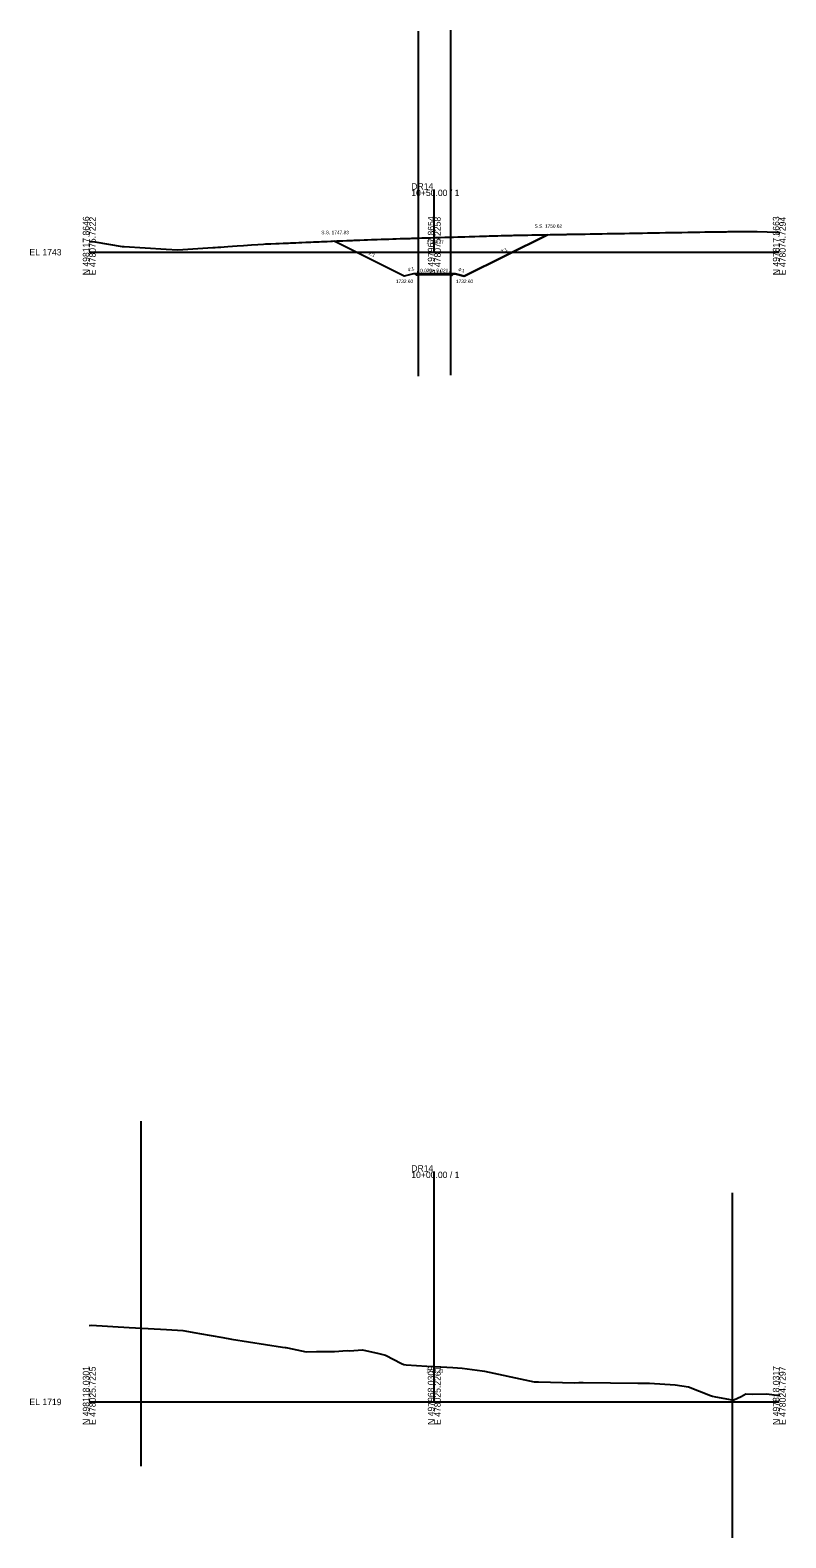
# Model space of a CAD drawing. Extents: x -26 to 303, y -59 to 3067.
# Drawn here: x -26 to 303, y -59 to 597 of the extents above; entities that cross this region are included whole.
import ezdxf

# ---------------------------------------------------------------- set-up
doc = ezdxf.new("R2010")
doc.units = 0
for name, color, linetype in [('Exist Cross Section Cell', 7, 'Continuous'), ('Exist XS Center Line Elevation Label', 7, 'Continuous'), ('Exist XS Ground Line', 7, 'Continuous'), ('Prop XS Ditch Slope Text', 7, 'Continuous'), ('Prop XS Ditch Standard Text', 7, 'Continuous'), ('Prop XS Earthwork Shape', 7, 'Continuous'), ('Prop XS EOT Tick Mark', 7, 'Continuous'), ('Prop XS Finish Grade', 7, 'Continuous'), ('Prop XS Finish Grade Earthwork', 7, 'Continuous'), ('Prop XS Finish Grade Pavement', 7, 'Continuous'), ('Prop XS Pvmt Edge Slope', 7, 'Continuous'), ('Prop XS SE Text', 7, 'Continuous'), ('Prop XS Shoulder Borrow Shape', 7, 'Continuous'), ('Prop XS Side Slope Text', 7, 'Continuous'), ('Prop XS SS Elevation Text', 7, 'Continuous'), ('Prop XS Subgrade Earthwork', 7, 'Continuous'), ('Scratch_Level_6', 7, 'Continuous')]:
    doc.layers.add(name, color=color, linetype=linetype)

msp = doc.modelspace()

# ---------------------------------------------------------------- linework, layer by layer
at = {"layer": 'Exist Cross Section Cell'}
for p, q in [((150, 500), (150, 527.23)), ((0, 500), (150, 500)), ((150, 500), (300, 500)), ((150, 0), (150, 100.16)), ((0, 0), (150, 0)), ((150, 0), (300, 0))]:
    msp.add_line(p, q, dxfattribs=at)
at = {"layer": 'Exist XS Ground Line'}
for points in [[(0, 504.72), (0.95, 504.63), (2.38, 504.49), (14.28, 502.52), (15.11, 502.47), (33.42, 501.31), (38.57, 501.07), (53.74, 502), (54.76, 502.07), (55.9, 502.15), (57.17, 502.25), (58.6, 502.35), (60.21, 502.47), (64.32, 502.76), (67.06, 502.95), (70.47, 503.18), (73.32, 503.37), (75.7, 503.53), (76.56, 503.59), (78.67, 503.67), (79, 503.69), (81.13, 503.77), (81.61, 503.79), (82.17, 503.81), (82.6, 503.83), (84.32, 503.9), (84.92, 503.93), (86.62, 504), (87.49, 504.03), (89.86, 504.14), (91.15, 504.19), (92.01, 504.23), (92.37, 504.24), (94.09, 504.31), (94.94, 504.35), (96.28, 504.4), (97.48, 504.45), (98.62, 504.5), (100, 504.56), (100.97, 504.6), (102.53, 504.67), (103.37, 504.7), (105.04, 504.77), (105.8, 504.8), (107.7, 504.89), (108.47, 504.92), (110.19, 504.99), (111.94, 505.06), (112.69, 505.09), (114.41, 505.16), (115.2, 505.19), (115.97, 505.22), (117.7, 505.29), (119.45, 505.36), (120.2, 505.38), (120.94, 505.41), (122.69, 505.48), (124.48, 505.55), (125.2, 505.57), (126.97, 505.63), (127.7, 505.66), (128.43, 505.68), (130.21, 505.74), (132.01, 505.8), (132.7, 505.83), (133.39, 505.85), (135.2, 505.91), (135.92, 505.93), (137.7, 505.99), (139.51, 506.04), (140.2, 506.07), (140.87, 506.09), (142.7, 506.14), (144.53, 506.2), (145.19, 506.22), (147.05, 506.28), (147.71, 506.3), (148.35, 506.32), (150.2, 506.38), (152.06, 506.43), (152.7, 506.45), (154.58, 506.51), (155.2, 506.53), (155.82, 506.54), (157.7, 506.6), (158.33, 506.62), (160.2, 506.67), (162.11, 506.73), (162.7, 506.75), (163.28, 506.76), (165.2, 506.82), (165.79, 506.84), (167.7, 506.9), (169.63, 506.95), (170.2, 506.97), (172.14, 507.03), (172.7, 507.04), (173.85, 507.08), (174.68, 507.1), (175.2, 507.12), (176.46, 507.15), (177.1, 507.17), (177.7, 507.18), (179.1, 507.22), (179.51, 507.23), (181.89, 507.3), (182.51, 507.31), (183.87, 507.34), (184.59, 507.35), (186.03, 507.38), (187.27, 507.4), (188.3, 507.42), (189.87, 507.45), (190.68, 507.47), (192.42, 507.5), (193.1, 507.51), (194.95, 507.54), (195.55, 507.55), (197.5, 507.59), (197.98, 507.6), (200.45, 507.65), (202.7, 507.69), (203.15, 507.7), (205.2, 507.74), (207.27, 507.77), (207.7, 507.79), (209.79, 507.82), (210.2, 507.83), (212.28, 507.86), (212.7, 507.87), (213.11, 507.88), (215.19, 507.91), (215.62, 507.92), (217.7, 507.95), (219.82, 507.98), (220.2, 507.99), (222.34, 508.03), (222.7, 508.03), (223.06, 508.04), (225.2, 508.08), (225.57, 508.08), (227.69, 508.12), (229.82, 508.15), (230.19, 508.16), (232.35, 508.2), (232.69, 508.2), (234.88, 508.24), (235.2, 508.25), (235.52, 508.25), (237.7, 508.29), (238.03, 508.29), (240.19, 508.33), (240.53, 508.34), (242.7, 508.37), (244.9, 508.41), (245.2, 508.41), (247.97, 508.46), (250.48, 508.51), (252.99, 508.56), (255.49, 508.6), (257.69, 508.64), (260.2, 508.69), (262.69, 508.73), (265.43, 508.78), (267.68, 508.81), (268.06, 508.82), (268.51, 508.82), (270.2, 508.85), (270.79, 508.86), (272.3, 508.88), (273.21, 508.89), (273.81, 508.9), (275.33, 508.92), (277.01, 508.94), (277.78, 508.95), (279.72, 508.97), (280.24, 508.98), (282.38, 509), (282.7, 509), (284.53, 509.02), (285.27, 509.03), (286.18, 509.04), (287.2, 509.05), (289.72, 509.08), (290.43, 509.04), (294.75, 508.86), (298.86, 508.69), (299.59, 508.67), (300, 508.65)], [(0, 33.28), (0.89, 33.39), (17.33, 32.44), (25.55, 31.95), (33.63, 31.57), (40.71, 31.01), (46.39, 30.08), (47.93, 29.78), (58.11, 27.96), (61.85, 27.26), (83.99, 23.84), (85.12, 23.67), (85.48, 23.65), (86.15, 23.49), (94.24, 21.81), (98.77, 21.96), (102.28, 21.92), (106.58, 21.95), (112.07, 22.34), (113.14, 22.18), (118.8, 22.6), (119.41, 22.53), (125.28, 21.18), (128.86, 20.35), (135.71, 16.79), (136.73, 16.33), (137.8, 16.07), (146.81, 15.63), (150, 15.43), (152.79, 15.26), (158.02, 14.93), (162.15, 14.71), (170.85, 13.53), (171.88, 13.32), (191.45, 9.14), (193.39, 8.75), (195.33, 8.79), (211.01, 8.34), (212.89, 8.42), (214.78, 8.51), (238.54, 8.19), (240.72, 8.23), (242.91, 8.22), (243.51, 8.21), (254.66, 7.48), (260.51, 6.53), (270.06, 2.77), (271.02, 2.54), (272.21, 2.28), (277.84, 1.22), (279.28, 0.9), (280.27, 0.91), (283.41, 2.39), (285.49, 3.46), (288.25, 3.34), (294.51, 3.47), (300, 2.77)]]:
    msp.add_lwpolyline(points, dxfattribs=at)
at = {"layer": 'Prop XS Earthwork Shape'}
msp.add_lwpolyline([(197.98, 507.6), (199.15, 507.62), (163.05, 489.6), (159.04, 490.6), (158.3, 490.66), (157.72, 490.08), (157.04, 490.09), (150, 490.23), (142.96, 490.09), (142.28, 490.08), (141.7, 490.66), (140.96, 490.6), (136.95, 489.6), (106.44, 504.83), (107.7, 504.89), (108.47, 504.92), (110.19, 504.99), (111.94, 505.06), (112.69, 505.09), (114.41, 505.16), (115.2, 505.19), (115.97, 505.22), (117.7, 505.29), (119.45, 505.36), (120.2, 505.38), (120.94, 505.41), (122.69, 505.48), (124.48, 505.55), (125.2, 505.57), (126.97, 505.63), (127.7, 505.66), (128.43, 505.68), (130.21, 505.74), (132.01, 505.8), (132.7, 505.83), (133.39, 505.85), (135.2, 505.91), (135.92, 505.93), (137.7, 505.99), (139.51, 506.04), (140.2, 506.07), (140.87, 506.09), (142.7, 506.14), (144.53, 506.2), (145.19, 506.22), (147.05, 506.28), (147.71, 506.3), (148.35, 506.32), (150.2, 506.38), (152.06, 506.43), (152.7, 506.45), (154.58, 506.51), (155.2, 506.53), (155.82, 506.54), (157.7, 506.6), (158.33, 506.62), (160.2, 506.67), (162.11, 506.73), (162.7, 506.75), (163.28, 506.76), (165.2, 506.82), (165.79, 506.84), (167.7, 506.9), (169.63, 506.95), (170.2, 506.97), (172.14, 507.03), (172.7, 507.04), (173.85, 507.08), (174.68, 507.1), (175.2, 507.12), (176.46, 507.15), (177.1, 507.17), (177.7, 507.18), (179.1, 507.22), (179.51, 507.23), (181.89, 507.3), (182.51, 507.31), (183.87, 507.34), (184.59, 507.35), (186.03, 507.38), (187.27, 507.4), (188.3, 507.42), (189.87, 507.45), (190.68, 507.47), (192.42, 507.5), (193.1, 507.51), (194.95, 507.54), (195.55, 507.55), (197.5, 507.59)], close=True, dxfattribs=at)
at = {"layer": 'Prop XS EOT Tick Mark'}
for p, q in [((142.96, 490.76), (142.96, 491.76)), ((157.04, 490.76), (157.04, 491.76))]:
    msp.add_line(p, q, dxfattribs=at)
at = {"layer": 'Prop XS Finish Grade'}
for p, q in [((142.96, 490.76), (141.7, 490.66)), ((157.04, 490.76), (158.3, 490.66))]:
    msp.add_line(p, q, dxfattribs=at)
at = {"layer": 'Prop XS Finish Grade Earthwork'}
for p, q in [((163.05, 489.6), (199.15, 507.62)), ((136.95, 489.6), (106.44, 504.83)), ((140.96, 490.6), (136.95, 489.6)), ((141.7, 490.66), (140.96, 490.6)), ((158.3, 490.66), (159.04, 490.6)), ((159.04, 490.6), (163.05, 489.6))]:
    msp.add_line(p, q, dxfattribs=at)
at = {"layer": 'Prop XS Finish Grade Pavement'}
for p, q in [((142.96, 490.76), (150, 490.9)), ((150, 490.9), (157.04, 490.76))]:
    msp.add_line(p, q, dxfattribs=at)
at = {"layer": 'Prop XS Pvmt Edge Slope'}
for p, q in [((142.96, 490.76), (142.28, 490.08)), ((157.04, 490.76), (157.72, 490.08))]:
    msp.add_line(p, q, dxfattribs=at)
at = {"layer": 'Prop XS Shoulder Borrow Shape'}
for points in [[(142.96, 490.76), (142.28, 490.08), (141.7, 490.66)], [(157.72, 490.08), (158.3, 490.66), (157.04, 490.76)]]:
    msp.add_lwpolyline(points, close=True, dxfattribs=at)
at = {"layer": 'Prop XS Subgrade Earthwork'}
for p, q in [((142.28, 490.08), (141.7, 490.66)), ((142.96, 490.09), (142.28, 490.08)), ((150, 490.23), (142.96, 490.09)), ((157.04, 490.09), (150, 490.23)), ((157.04, 490.09), (157.72, 490.08)), ((157.72, 490.08), (158.3, 490.66))]:
    msp.add_line(p, q, dxfattribs=at)
at = {"layer": 'Scratch_Level_6'}
for p, q in [((142.96, 596.15), (142.96, 446.15)), ((157.04, 596.58), (157.04, 446.58)), ((22.44, 122.14), (22.44, -27.86)), ((279.56, 90.9), (279.56, -59.1))]:
    msp.add_line(p, q, dxfattribs=at)

# ---------------------------------------------------------------- texts
at = {"layer": 'Exist Cross Section Cell'}
for s, p in [('10+50.00 / 1', (140, 524.43)), ('DR14', (140, 527.23)), ('EL 1743', (-26, 498.6)), ('10+00.00 / 1', (140, 97.36)), ('DR14', (140, 100.16)), ('EL 1719', (-26, -1.4))]:
    msp.add_text(s, height=2.8, dxfattribs=at).set_placement(p)
for s, p in [('N 498117.8646', (0, 490)), ('E 478075.7222', (2.8, 490)), ('N 497967.8654', (150, 490)), ('E 478075.2258', (152.8, 490)), ('N 497817.8663', (300, 490)), ('E 478074.7294', (302.8, 490)), ('N 498118.0301', (0, -10)), ('E 478025.7225', (2.8, -10)), ('N 497968.0309', (150, -10)), ('E 478025.2261', (152.8, -10)), ('N 497818.0317', (300, -10)), ('E 478024.7297', (302.8, -10))]:
    msp.add_text(s, height=2.8, rotation=90, dxfattribs=at).set_placement(p)
at = {"layer": 'Exist XS Center Line Elevation Label'}
for s, p in [('1749.37', (146.58, 503.62)), ('1734.43', (146.46, 12.68))]:
    msp.add_text(s, height=1.5, dxfattribs=at).set_placement(p)
at = {"layer": 'Prop XS Ditch Slope Text'}
for rotation, p in [(14.01942, (138.59, 491.55)), (345.98058, (160.26, 491.84))]:
    msp.add_text('4:1', height=1.5, rotation=rotation, dxfattribs=at).set_placement(p)
at = {"layer": 'Prop XS Ditch Standard Text'}
for p in [(133.32, 486.6), (159.42, 486.6)]:
    msp.add_text('1732.60', height=1.5, dxfattribs=at).set_placement(p)
at = {"layer": 'Prop XS SE Text'}
for rotation, p in [(1.14576, (143.86, 491.28)), (358.85424, (150.9, 491.38))]:
    msp.add_text('0.020', height=1.5, rotation=rotation, dxfattribs=at).set_placement(p)
at = {"layer": 'Prop XS Side Slope Text'}
for rotation, p in [(333.46355, (121.3, 499.09)), (26.53645, (179.36, 499.42))]:
    msp.add_text('2:1', height=1.5, rotation=rotation, dxfattribs=at).set_placement(p)
at = {"layer": 'Prop XS SS Elevation Text'}
for s, p in [('S.S. 1750.62', (193.61, 510.62)), ('S.S. 1747.83', (100.88, 507.83))]:
    msp.add_text(s, height=1.5, dxfattribs=at).set_placement(p)

doc.saveas('drawing.dxf')
